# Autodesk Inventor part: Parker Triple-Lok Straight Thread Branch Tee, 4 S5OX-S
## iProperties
Shininess: 64.0
Length Units: 11272
Angle Units: 11279
Time Units: 11290
Mass Units: 11286
Length Display Precision: 3
Angle Display Precision: 2
Created: 2001-12
Part Number: Parker Triple-Lok Straight Thread Branch Tee, 4 S5OX-S
Description: Parker Triple-Lok Straight Thread Branch Tee, 4 S5OX-S
Document SubType Name: Modeling
Designer: Administrator
Density: 0.0
Volumn: 0.0
Area: 0.0
PropertySet Name: Model Information
Control State: 0
Master: False
Checked Out: False
Last Check In By: Charles Bliss
Last Check In Date: 2003-09-27
Author: Administrator
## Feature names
1. Extrusion1
2. Extrusion2
3. Revolution2
4. Mirror3
5. Fillet1
6. Revolution3
7. Extrusion3
8. Revolution4
9. Mirror4
10. Extrusion4
11. Extrusion5
12. Chamfer1
13. Hole1
14. Hole2
15. Revolution8
